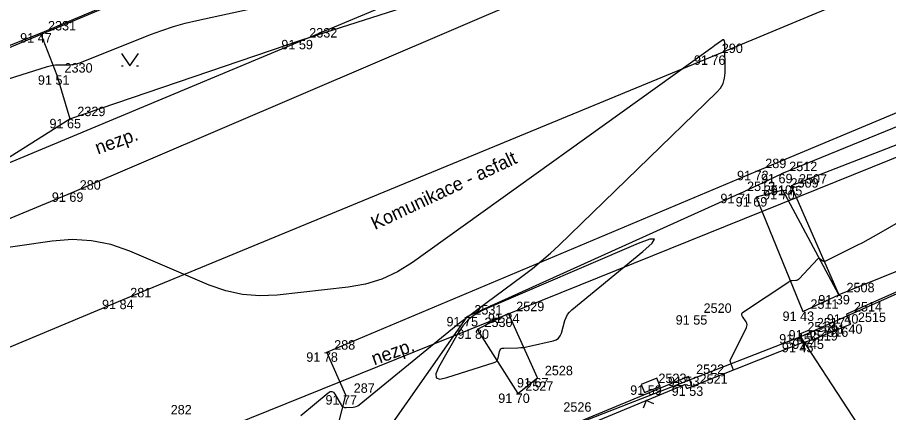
# Model space of a CAD drawing. Extents: x -711081 to -709338, y -1025122 to -1024092.
# Drawn here: x -710604.9 to -710579.05, y -1024867.14 to -1024855.43 of the extents above; entities that cross this region are included whole.
import ezdxf

# ---------------------------------------------------------------- set-up
doc = ezdxf.new("R2010")
doc.units = 0
for name, color, linetype in [('Ex_Minor Contours', 7, 'Continuous'), ('Z_body', 7, 'Continuous'), ('Z_body_cisla', 7, 'Continuous'), ('Z_body_vysky_redukovane', 7, 'Continuous'), ('Z_budova', 7, 'Continuous'), ('Z_katastr_hranice', 7, 'Continuous'), ('Z_katastr_hranice_katastralniho_uzemi', 7, 'Continuous'), ('Z_katastr_vnitrni_kresba', 7, 'Continuous'), ('Z_komunikace', 7, 'Continuous'), ('Z_komunikace_osa', 7, 'Continuous'), ('Z_pilire', 7, 'Continuous'), ('Z_ploty', 7, 'Continuous'), ('Z_ploty_znacky', 7, 'Continuous'), ('Z_popisy', 7, 'Continuous'), ('Z_rozhranni', 7, 'Continuous'), ('Z_vstupy', 7, 'Continuous'), ('Z_zelen_obvod', 7, 'Continuous'), ('Z_znaky_kultur', 7, 'Continuous')]:
    doc.layers.add(name, color=color, linetype=linetype)

# ---------------------------------------------------------------- blocks, each defined once
blk = doc.blocks.new('POINT_DISPLAY')
blk.add_line((0, 0), (0, 0))
blk = doc.blocks.new('Z666')
for p, q in [((-0.25, 0.13), (-0.25, -0.13)), ((0.25, 0.13), (-0.25, 0.13)), ((0.25, -0.13), (0.25, 0.13)), ((-0.25, -0.13), (0.25, -0.13))]:
    blk.add_line(p, q)
blk = doc.blocks.new('Z212')
for p, q in [((-0.17, 0.17), (0, 0)), ((0, 0), (0.17, 0.17))]:
    blk.add_line(p, q)
blk = doc.blocks.new('Z314')
for p, q in [((-0.25, 0.17), (0, -0.2)), ((0, -0.2), (0.25, 0.17)), ((-0.25, -0.2), (-0.2, -0.2)), ((0.2, -0.2), (0.25, -0.2))]:
    blk.add_line(p, q)

msp = doc.modelspace()

# ---------------------------------------------------------------- linework, layer by layer
at = {"layer": 'Ex_Minor Contours'}
for points in [[(-710608.856, -1024858.417), (-710604.005, -1024856.886), (-710603.927, -1024856.865), (-710603.848, -1024856.85), (-710603.768, -1024856.84), (-710603.688, -1024856.837), (-710603.363, -1024856.837), (-710603.283, -1024856.833), (-710603.204, -1024856.822), (-710603.126, -1024856.803), (-710603.05, -1024856.777), (-710600.95, -1024855.944), (-710600.612, -1024855.818), (-710600.269, -1024855.706), (-710599.922, -1024855.607), (-710599.571, -1024855.523), (-710597.614, -1024855.096)], [(-710596.493, -1024867.228), (-710595.676, -1024866.559), (-710595.618, -1024866.524), (-710595.566, -1024866.519), (-710595.519, -1024866.542), (-710595.478, -1024866.596), (-710595.297, -1024866.913), (-710595.268, -1024866.952), (-710595.233, -1024866.979), (-710595.192, -1024866.994), (-710595.144, -1024866.997), (-710594.94, -1024866.987), (-710594.891, -1024866.98), (-710594.844, -1024866.967), (-710594.8, -1024866.946), (-710594.76, -1024866.917), (-710592.096, -1024864.747), (-710591.827, -1024864.53), (-710591.555, -1024864.317), (-710591.28, -1024864.107), (-710591.003, -1024863.9), (-710589.888, -1024863.08), (-710589.613, -1024862.871), (-710589.345, -1024862.652), (-710589.085, -1024862.425), (-710588.833, -1024862.189), (-710584.144, -1024857.651), (-710584.038, -1024857.527), (-710583.962, -1024857.389), (-710583.917, -1024857.239), (-710583.903, -1024857.075), (-710583.912, -1024856.177), (-710583.919, -1024856.128), (-710583.937, -1024856.103), (-710583.968, -1024856.103), (-710584.012, -1024856.127), (-710584.209, -1024856.27), (-710584.258, -1024856.306), (-710584.308, -1024856.342), (-710584.357, -1024856.377), (-710584.407, -1024856.413), (-710593.178, -1024862.696), (-710593.619, -1024862.973), (-710594.084, -1024863.187), (-710594.574, -1024863.339), (-710595.087, -1024863.429), (-710597.187, -1024863.663), (-710597.707, -1024863.688), (-710598.217, -1024863.647), (-710598.718, -1024863.54), (-710599.209, -1024863.366), (-710601.565, -1024862.364), (-710602.125, -1024862.168), (-710602.695, -1024862.053), (-710603.276, -1024862.019), (-710603.867, -1024862.064), (-710606.893, -1024862.502)], [(-710583.654, -1024865.886), (-710583.713, -1024865.729), (-710583.718, -1024865.717), (-710583.722, -1024865.705), (-710583.726, -1024865.693), (-710583.73, -1024865.681), (-710583.745, -1024865.632), (-710583.748, -1024865.62), (-710583.748, -1024865.608), (-710583.746, -1024865.596), (-710583.741, -1024865.585), (-710583.268, -1024864.627), (-710583.253, -1024864.584), (-710583.249, -1024864.541), (-710583.258, -1024864.5), (-710583.279, -1024864.459), (-710583.386, -1024864.296), (-710583.404, -1024864.257), (-710583.405, -1024864.221), (-710583.39, -1024864.189), (-710583.358, -1024864.16), (-710582.01, -1024863.268), (-710581.987, -1024863.254), (-710581.962, -1024863.244), (-710581.936, -1024863.236), (-710581.91, -1024863.232), (-710581.8, -1024863.222), (-710581.774, -1024863.217), (-710581.75, -1024863.208), (-710581.728, -1024863.195), (-710581.708, -1024863.177), (-710581.153, -1024862.592), (-710581.136, -1024862.578), (-710581.118, -1024862.573), (-710581.099, -1024862.575), (-710581.079, -1024862.586), (-710581, -1024862.644), (-710580.98, -1024862.655), (-710580.96, -1024862.66), (-710580.939, -1024862.659), (-710580.917, -1024862.651), (-710579.98, -1024862.183), (-710579.817, -1024862.101), (-710579.656, -1024862.016), (-710579.496, -1024861.928), (-710579.337, -1024861.838), (-710576.28, -1024860.081)]]:
    msp.add_lwpolyline(points, dxfattribs=at)
msp.add_lwpolyline([(-710592.484, -1024866.002), (-710592.47, -1024866.115), (-710592.362, -1024866.151), (-710592.159, -1024866.11), (-710590.751, -1024865.661), (-710590.708, -1024865.641), (-710590.674, -1024865.613), (-710590.649, -1024865.576), (-710590.634, -1024865.531), (-710590.592, -1024865.333), (-710590.577, -1024865.289), (-710590.551, -1024865.258), (-710590.516, -1024865.239), (-710590.47, -1024865.232), (-710590.049, -1024865.224), (-710589.962, -1024865.221), (-710589.876, -1024865.212), (-710589.79, -1024865.199), (-710589.705, -1024865.182), (-710589.001, -1024865.02), (-710588.914, -1024864.99), (-710588.845, -1024864.941), (-710588.793, -1024864.874), (-710588.758, -1024864.789), (-710588.654, -1024864.413), (-710588.621, -1024864.323), (-710588.577, -1024864.242), (-710588.52, -1024864.168), (-710588.451, -1024864.102), (-710586.341, -1024862.371), (-710586.067, -1024862.124), (-710586, -1024862.003), (-710586.139, -1024862.007), (-710586.484, -1024862.136), (-710591.043, -1024864.089), (-710591.287, -1024864.216), (-710591.5, -1024864.377), (-710591.682, -1024864.572), (-710591.835, -1024864.8), (-710592.402, -1024865.811)], close=True, dxfattribs=at)
at = {"layer": 'Z_budova'}
for p, q in [((-710604.21, -1024855.9), (-710598.64, -1024853.55)), ((-710609.49, -1024857.99), (-710604.21, -1024855.9)), ((-710574.88, -1024861.81), (-710580.3, -1024864.23)), ((-710580.3, -1024864.23), (-710580.18, -1024864.53))]:
    msp.add_line(p, q, dxfattribs=at)
at = {"layer": 'Z_katastr_hranice'}
for p, q in [((-710640.42, -1024884.4), (-710562.9, -1024853.16)), ((-710609.5, -1024858.14), (-710597.39, -1024853.09)), ((-710574.9, -1024861.89), (-710581.66, -1024864.9)), ((-710581.66, -1024864.9), (-710588.87, -1024867.71))]:
    msp.add_line(p, q, dxfattribs=at)
at = {"layer": 'Z_katastr_hranice_katastralniho_uzemi'}
msp.add_line((-710587.89, -1024852.54), (-710688.39, -1024894.53), dxfattribs=at)
msp.add_line((-710587.89, -1024852.54), (-710688.39, -1024894.53), dxfattribs=at)
at = {"layer": 'Z_katastr_vnitrni_kresba'}
msp.add_line((-710581.66, -1024864.9), (-710579.62, -1024868.03), dxfattribs=at)
at = {"layer": 'Z_komunikace'}
for p, q in [((-710582.94, -1024859.98), (-710565.61, -1024852.72)), ((-710603.27, -1024860.62), (-710585.62, -1024853.07)), ((-710595.72, -1024865.36), (-710582.94, -1024859.98)), ((-710616.68, -1024866.18), (-710603.27, -1024860.62)), ((-710595.15, -1024866.63), (-710595.72, -1024865.36)), ((-710595.39, -1024867.56), (-710595.15, -1024866.63))]:
    msp.add_line(p, q, dxfattribs=at)
at = {"layer": 'Z_komunikace_osa'}
for p, q in [((-710584.22, -1024856.56), (-710567.13, -1024849.45)), ((-710601.78, -1024863.8), (-710584.22, -1024856.56)), ((-710615.69, -1024869.61), (-710601.78, -1024863.8))]:
    msp.add_line(p, q, dxfattribs=at)
at = {"layer": 'Z_ploty'}
for p, q in [((-710581.41, -1024864.7), (-710581.69, -1024864.82)), ((-710581.69, -1024864.82), (-710581.61, -1024865.08)), ((-710581.3, -1024864.98), (-710581.41, -1024864.7)), ((-710581.61, -1024865.08), (-710581.3, -1024864.98)), ((-710584.99, -1024866.08), (-710588.87, -1024867.69)), ((-710584.88, -1024866.37), (-710584.99, -1024866.08)), ((-710585.09, -1024866.31), (-710588.8, -1024867.85)), ((-710585.04, -1024866.43), (-710585.09, -1024866.31)), ((-710585.04, -1024866.43), (-710584.88, -1024866.37))]:
    msp.add_line(p, q, dxfattribs=at)
at = {"layer": 'Z_rozhranni'}
for p, q in [((-710596.46, -1024856.1), (-710589.38, -1024853.83)), ((-710603.34, -1024858.44), (-710596.46, -1024856.1)), ((-710606.76, -1024860.59), (-710603.34, -1024858.44)), ((-710578.37, -1024858.49), (-710582.23, -1024860.07)), ((-710583.48, -1024860.66), (-710582.23, -1024860.07)), ((-710582.19, -1024860.55), (-710582.98, -1024860.76)), ((-710580.53, -1024863.66), (-710582.19, -1024860.55)), ((-710583.48, -1024860.66), (-710591.56, -1024864.31)), ((-710582.98, -1024860.76), (-710581.59, -1024864.15)), ((-710575.14, -1024861.48), (-710580.53, -1024863.66)), ((-710581.59, -1024864.15), (-710580.53, -1024863.66)), ((-710591.56, -1024864.31), (-710594.06, -1024867.86))]:
    msp.add_line(p, q, dxfattribs=at)
at = {"layer": 'Z_vstupy'}
for p, q in [((-710581.3, -1024864.98), (-710580.18, -1024864.53)), ((-710581.61, -1024865.08), (-710584.88, -1024866.37))]:
    msp.add_line(p, q, dxfattribs=at)
at = {"layer": 'Z_zelen_obvod'}
for p, q in [((-710604.21, -1024855.9), (-710603.73, -1024857.15)), ((-710603.73, -1024857.15), (-710603.34, -1024858.44)), ((-710577.98, -1024858.89), (-710581.94, -1024860.43)), ((-710581.94, -1024860.43), (-710580.53, -1024863.66)), ((-710590.33, -1024864.21), (-710591.26, -1024864.68)), ((-710589.47, -1024866.12), (-710590.33, -1024864.21)), ((-710591.26, -1024864.68), (-710590.05, -1024866.58)), ((-710590.05, -1024866.58), (-710589.47, -1024866.12))]:
    msp.add_line(p, q, dxfattribs=at)

# ---------------------------------------------------------------- block references
at = {"layer": 'Z_body'}
for p in [(-710604.21, -1024855.9), (-710596.46, -1024856.1), (-710584.22, -1024856.56), (-710603.73, -1024857.15), (-710603.34, -1024858.44), (-710582.94, -1024859.98), (-710582.23, -1024860.07), (-710582.19, -1024860.55), (-710581.94, -1024860.43), (-710603.27, -1024860.62), (-710583.48, -1024860.66), (-710582.98, -1024860.76), (-710601.78, -1024863.8), (-710580.53, -1024863.66), (-710581.59, -1024864.15), (-710591.56, -1024864.31), (-710590.33, -1024864.21), (-710584.76, -1024864.26), (-710580.3, -1024864.23), (-710591.26, -1024864.68), (-710580.18, -1024864.53), (-710581.69, -1024864.82), (-710581.41, -1024864.7), (-710581.61, -1024865.08), (-710581.3, -1024864.98), (-710595.72, -1024865.36), (-710589.47, -1024866.12), (-710584.99, -1024866.08), (-710586.11, -1024866.34), (-710584.88, -1024866.37), (-710595.15, -1024866.63), (-710590.05, -1024866.58)]:
    msp.add_blockref('POINT_DISPLAY', p, dxfattribs=at)
at = {"layer": 'Z_pilire', "rotation": 21.6}
msp.add_blockref('Z666', (-710586.11, -1024866.34), dxfattribs=at)
at = {"layer": 'Z_ploty_znacky', "rotation": -157.50000000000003}
msp.add_blockref('Z212', (-710586.24, -1024866.79), dxfattribs=at)
at = {"layer": 'Z_znaky_kultur'}
msp.add_blockref('Z314', (-710601.56, -1024856.67), dxfattribs=at)

# ---------------------------------------------------------------- texts
at = {"layer": 'Z_body_cisla'}
for s, p in [('2331', (-710603.99, -1024855.82)), ('2332', (-710596.24, -1024856.03)), ('290', (-710584, -1024856.49)), ('2330', (-710603.5, -1024857.07)), ('2329', (-710603.12, -1024858.36)), ('289', (-710582.71, -1024859.9)), ('2512', (-710582, -1024859.99)), ('280', (-710603.05, -1024860.54)), ('2509', (-710581.96, -1024860.48)), ('2507', (-710581.71, -1024860.36)), ('2513', (-710583.25, -1024860.58)), ('2510', (-710582.75, -1024860.69)), ('2508', (-710580.3, -1024863.58)), ('281', (-710601.55, -1024863.73)), ('2529', (-710590.1, -1024864.14)), ('2520', (-710584.54, -1024864.19)), ('2511', (-710581.37, -1024864.07)), ('2514', (-710580.08, -1024864.15)), ('2531', (-710591.34, -1024864.24)), ('2530', (-710591.04, -1024864.61)), ('2517', (-710581.18, -1024864.62)), ('2515', (-710579.96, -1024864.46)), ('2518', (-710581.46, -1024864.74)), ('2516', (-710581.08, -1024864.9)), ('2519', (-710581.39, -1024865.01)), ('288', (-710595.5, -1024865.28)), ('2522', (-710584.76, -1024866)), ('2528', (-710589.25, -1024866.04)), ('2527', (-710589.83, -1024866.5)), ('2523', (-710585.88, -1024866.27)), ('2521', (-710584.66, -1024866.29)), ('287', (-710594.92, -1024866.56)), ('282', (-710600.35, -1024867.2)), ('2526', (-710588.7, -1024867.12))]:
    msp.add_text(s, height=0.28, dxfattribs=at).set_placement(p)
at = {"layer": 'Z_body_vysky_redukovane'}
for s, p in [('91 47', (-710604.817, -1024856.18)), ('91 59', (-710597.067, -1024856.38)), ('91 76', (-710584.827, -1024856.84)), ('91 51', (-710604.29, -1024857.43)), ('91 65', (-710603.947, -1024858.72)), ('91 72', (-710583.547, -1024860.26)), ('91 69', (-710582.837, -1024860.35)), ('91 70', (-710582.773, -1024860.83)), ('91 75', (-710582.547, -1024860.71)), ('91 69', (-710603.877, -1024860.9)), ('91 71', (-710584.04, -1024860.94)), ('91 69', (-710583.587, -1024861.04)), ('91 84', (-710602.387, -1024864.08)), ('91 39', (-710581.137, -1024863.94)), ('91 43', (-710582.197, -1024864.43)), ('91 75', (-710592.167, -1024864.59)), ('91 84', (-710590.937, -1024864.49)), ('91 55', (-710585.367, -1024864.54)), ('91 40', (-710580.883, -1024864.51)), ('91 80', (-710591.843, -1024864.96)), ('91 40', (-710580.763, -1024864.81)), ('91 45', (-710582.297, -1024865.1)), ('91 45', (-710582.017, -1024864.98)), ('91 45', (-710582.217, -1024865.36)), ('91 45', (-710581.907, -1024865.26)), ('91 78', (-710596.327, -1024865.64)), ('91 67', (-710590.077, -1024866.4)), ('91 53', (-710585.597, -1024866.36)), ('91 59', (-710586.717, -1024866.62)), ('91 53', (-710585.487, -1024866.65)), ('91 77', (-710595.757, -1024866.91)), ('91 70', (-710590.633, -1024866.86))]:
    msp.add_text(s, height=0.28, dxfattribs=at).set_placement(p)
at = {"layer": 'Z_popisy'}
for s, rotation, p in [('nezp.', 19.8, (-710602.51, -1024859.5)), ('Komunikace - asfalt', 25.2, (-710594.29, -1024861.74)), ('nezp.', 19.8, (-710594.31, -1024865.75))]:
    msp.add_text(s, height=0.4, rotation=rotation, dxfattribs=at).set_placement(p)

doc.saveas('drawing.dxf')
